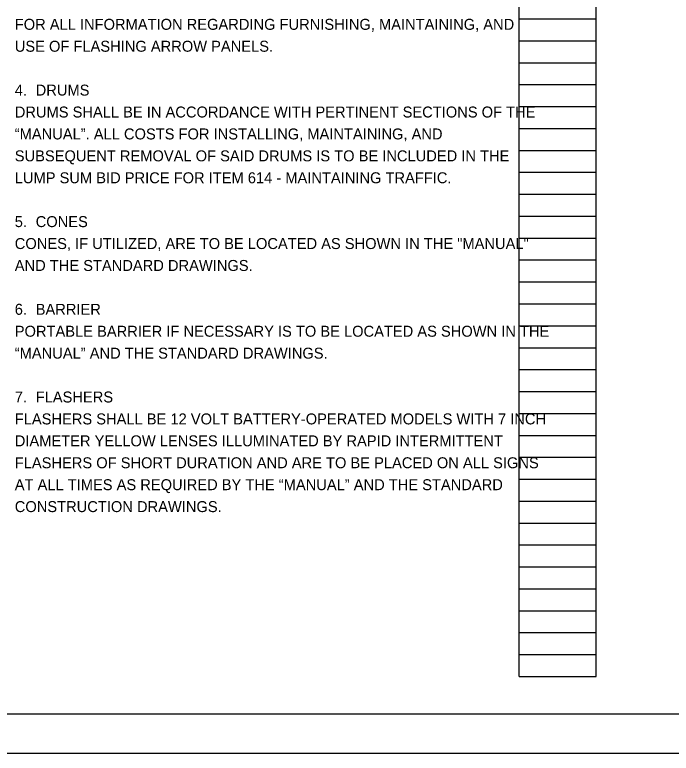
# Model space of a CAD drawing. Extents: x -15.1 to 34, y -7.8 to 43.8.
# Drawn here: x 17.24 to 25.62, y 0 to 9.43 of the extents above; entities that cross this region are included whole.
import ezdxf

# ---------------------------------------------------------------- set-up
doc = ezdxf.new("R2010")
doc.units = 0
for name, color, linetype in [('SH_Border', 7, 'Continuous'), ('SH_Cut_Line', 7, 'Continuous'), ('SH_Data', 7, 'Continuous'), ('SH_Text', 7, 'Continuous')]:
    doc.layers.add(name, color=color, linetype=linetype)

msp = doc.modelspace()

# ---------------------------------------------------------------- linework, layer by layer
at = {"layer": 'SH_Border'}
msp.add_lwpolyline([(1.5, 21.5), (33.5, 21.5), (33.5, 0.5), (1.5, 0.5)], close=True, dxfattribs=at)
at = {"layer": 'SH_Cut_Line'}
msp.add_lwpolyline([(0, 0), (34, 0), (34, 22), (0, 22)], close=True, dxfattribs=at)
at = {"layer": 'SH_Data'}
for p, q in [((23.68, 0.98), (23.68, 21.14)), ((24.66, 0.98), (24.66, 21.14)), ((23.68, 9.38), (24.66, 9.38)), ((23.68, 9.1), (24.66, 9.1)), ((23.68, 8.82), (24.66, 8.82)), ((23.68, 8.54), (24.66, 8.54)), ((23.68, 8.26), (24.66, 8.26)), ((23.68, 7.98), (24.66, 7.98)), ((23.68, 7.7), (24.66, 7.7)), ((23.68, 7.42), (24.66, 7.42)), ((23.68, 7.14), (24.66, 7.14)), ((23.68, 6.86), (24.66, 6.86)), ((23.68, 6.58), (24.66, 6.58)), ((23.68, 6.3), (24.66, 6.3)), ((23.68, 6.02), (24.66, 6.02)), ((23.68, 5.74), (24.66, 5.74)), ((23.68, 5.46), (24.66, 5.46)), ((23.68, 5.18), (24.66, 5.18)), ((23.68, 4.9), (24.66, 4.9)), ((23.68, 4.62), (24.66, 4.62)), ((23.68, 4.34), (24.66, 4.34)), ((23.68, 4.06), (24.66, 4.06)), ((23.68, 3.78), (24.66, 3.78)), ((23.68, 3.5), (24.66, 3.5)), ((23.68, 3.22), (24.66, 3.22)), ((23.68, 2.94), (24.66, 2.94)), ((23.68, 2.66), (24.66, 2.66)), ((23.68, 2.38), (24.66, 2.38)), ((23.68, 2.1), (24.66, 2.1)), ((23.68, 1.82), (24.66, 1.82)), ((23.68, 1.54), (24.66, 1.54)), ((23.68, 1.26), (24.66, 1.26)), ((23.68, 0.98), (24.66, 0.98))]:
    msp.add_line(p, q, dxfattribs=at)

# ---------------------------------------------------------------- texts
at = {"layer": 'SH_Text'}
for s, p in [('FOR ALL INFORMATION REGARDING FURNISHING, MAINTAINING, AND ', (17.24, 9.24)), ('USE OF FLASHING ARROW PANELS. ', (17.24, 8.96)), ('4.  ', (17.24, 8.4)), ('DRUMS', (17.5071, 8.4)), ('DRUMS SHALL BE IN ACCORDANCE WITH PERTINENT SECTIONS OF THE ', (17.24, 8.12)), ('“MANUAL”. ALL COSTS FOR INSTALLING, MAINTAINING, AND ', (17.24, 7.84)), ('SUBSEQUENT REMOVAL OF SAID DRUMS IS TO BE INCLUDED IN THE ', (17.24, 7.56)), ('LUMP SUM BID PRICE FOR ITEM 614 - MAINTAINING TRAFFIC. ', (17.24, 7.28)), ('5.  ', (17.24, 6.72)), ('CONES', (17.5071, 6.72)), ('CONES, IF UTILIZED, ARE TO BE LOCATED AS SHOWN IN THE "MANUAL" ', (17.24, 6.44)), ('AND THE STANDARD DRAWINGS.', (17.24, 6.16)), ('6.  ', (17.24, 5.6)), ('BARRIER', (17.5071, 5.6)), ('PORTABLE BARRIER IF NECESSARY IS TO BE LOCATED AS SHOWN IN THE ', (17.24, 5.32)), ('“MANUAL” AND THE STANDARD DRAWINGS. ', (17.24, 5.04)), ('FLASHERS', (17.5071, 4.48)), ('7.  ', (17.24, 4.48)), ('FLASHERS SHALL BE 12 VOLT BATTERY-OPERATED MODELS WITH 7 INCH ', (17.24, 4.2)), ('DIAMETER YELLOW LENSES ILLUMINATED BY RAPID INTERMITTENT ', (17.24, 3.92)), ('FLASHERS OF SHORT DURATION AND ARE TO BE PLACED ON ALL SIGNS ', (17.24, 3.64)), ('AT ALL TIMES AS REQUIRED BY THE “MANUAL” AND THE STANDARD ', (17.24, 3.36)), ('CONSTRUCTION DRAWINGS. ', (17.24, 3.08))]:
    msp.add_text(s, height=0.14, dxfattribs=at).set_placement(p)

doc.saveas('drawing.dxf')
